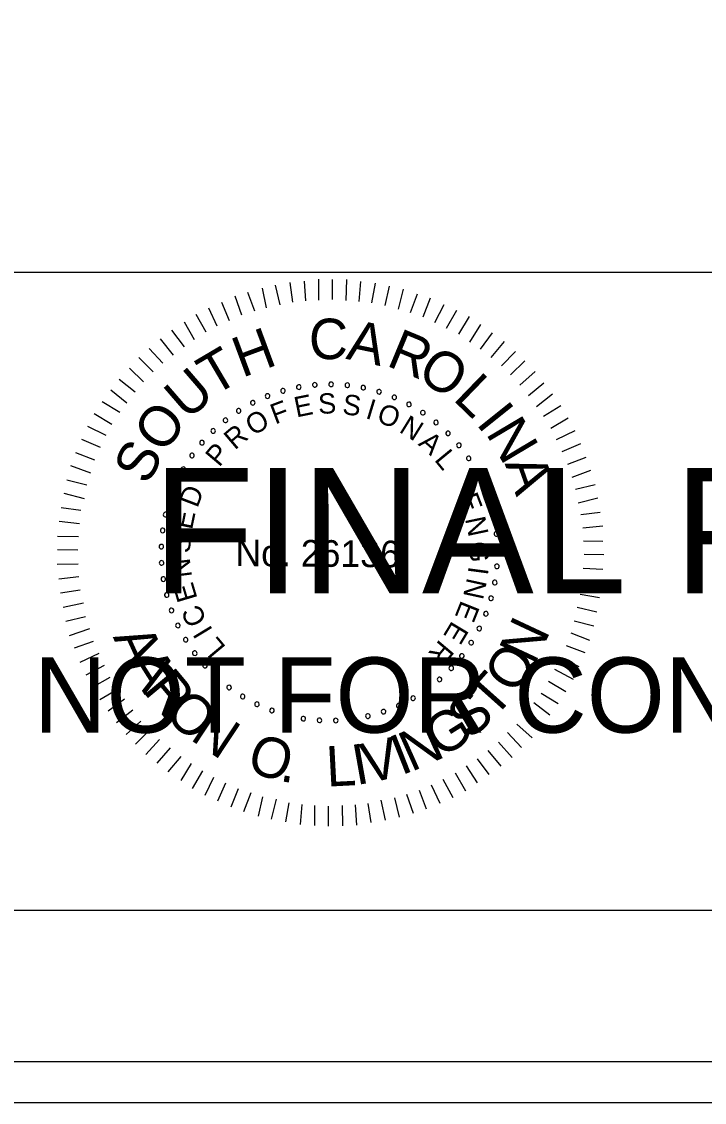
# Model space of a CAD drawing. Extents: x 967 to 1746, y 964 to 7904.
# Drawn here: x 1170.56 to 1189.3, y 7123.72 to 7153.36 of the extents above; entities that cross this region are included whole.
import ezdxf

# ---------------------------------------------------------------- set-up
doc = ezdxf.new("R2010")
doc.units = 0
for name, color, linetype in [('RD_SHT_Bndy', 7, 'Continuous'), ('RD_SHT_IplotShp', 7, 'Continuous'), ('RD_SHT_Misc1', 7, 'Continuous'), ('RD_SHT_Misc2', 7, 'Continuous'), ('RD_Sketch1', 7, 'Continuous')]:
    doc.layers.add(name, color=color, linetype=linetype)

msp = doc.modelspace()

# ---------------------------------------------------------------- linework, layer by layer
at = {"layer": 'RD_SHT_Bndy'}
for p, q in [((996.114, 7146.486), (1323.886, 7146.486)), ((1323.886, 7128.983), (996.114, 7128.983))]:
    msp.add_line(p, q, dxfattribs=at)
at = {"layer": 'RD_SHT_IplotShp'}
for points in [[(967.409, 7123.72), (1326.285, 7123.72), (1326.285, 7343.72), (967.409, 7343.72)], [(988.525, 7124.84), (1326.285, 7124.84), (1326.285, 7342.6), (988.525, 7342.6)]]:
    msp.add_lwpolyline(points, close=True, dxfattribs=at)
at = {"layer": 'RD_SHT_Misc1'}
for p, q in [((1178.01, 7145.663), (1177.93, 7146.209)), ((1178.364, 7145.699), (1178.33, 7146.244)), ((1178.717, 7145.719), (1178.722, 7146.295)), ((1179.093, 7145.739), (1179.098, 7146.292)), ((1179.469, 7145.713), (1179.489, 7146.288)), ((1179.829, 7145.687), (1179.872, 7146.231)), ((1180.174, 7145.646), (1180.271, 7146.19)), ((1176.964, 7145.419), (1176.769, 7145.935)), ((1177.287, 7145.508), (1177.169, 7146.054)), ((1177.657, 7145.597), (1177.53, 7146.128)), ((1180.535, 7145.573), (1180.662, 7146.102)), ((1180.902, 7145.478), (1181.045, 7146.022)), ((1181.231, 7145.384), (1181.428, 7145.896)), ((1176.264, 7145.156), (1176.053, 7145.657)), ((1176.61, 7145.306), (1176.423, 7145.83)), ((1181.584, 7145.265), (1181.78, 7145.786)), ((1181.905, 7145.109), (1182.154, 7145.606)), ((1175.624, 7144.846), (1175.352, 7145.332)), ((1175.933, 7145.005), (1175.699, 7145.506)), ((1182.226, 7144.953), (1182.506, 7145.45)), ((1182.562, 7144.789), (1182.85, 7145.27)), ((1175.308, 7144.634), (1175.036, 7145.12)), ((1182.86, 7144.572), (1183.163, 7145.053)), ((1174.729, 7144.217), (1174.372, 7144.665)), ((1175.03, 7144.445), (1174.681, 7144.9)), ((1183.158, 7144.378), (1183.484, 7144.828)), ((1174.435, 7143.997), (1174.062, 7144.399)), ((1183.447, 7144.145), (1183.811, 7144.587)), ((1174.172, 7143.753), (1173.776, 7144.148)), ((1183.729, 7143.92), (1184.116, 7144.316)), ((1173.909, 7143.479), (1173.52, 7143.858)), ((1183.98, 7143.672), (1184.368, 7144.061)), ((1173.684, 7143.197), (1173.242, 7143.546)), ((1184.232, 7143.394), (1184.657, 7143.767)), ((1173.451, 7142.9), (1173.009, 7143.256)), ((1184.475, 7143.108), (1184.892, 7143.45)), ((1173.257, 7142.64), (1172.776, 7142.936)), ((1184.687, 7142.807), (1185.128, 7143.156)), ((1173.039, 7142.312), (1172.559, 7142.6)), ((1184.885, 7142.544), (1185.355, 7142.832)), ((1185.081, 7142.213), (1185.56, 7142.493)), ((1172.883, 7142.006), (1172.379, 7142.256)), ((1185.24, 7141.904), (1185.756, 7142.145)), ((1172.727, 7141.677), (1172.215, 7141.904)), ((1185.399, 7141.573), (1185.907, 7141.791)), ((1172.571, 7141.333), (1172.051, 7141.53)), ((1185.549, 7141.226), (1186.057, 7141.414)), ((1172.461, 7140.974), (1171.91, 7141.178)), ((1185.669, 7140.865), (1186.185, 7141.06)), ((1172.351, 7140.652), (1171.807, 7140.787)), ((1185.759, 7140.541), (1186.297, 7140.667)), ((1172.286, 7140.276), (1171.727, 7140.419)), ((1185.832, 7140.165), (1186.371, 7140.298)), ((1172.191, 7139.955), (1171.647, 7140.029)), ((1172.15, 7139.587), (1171.598, 7139.653)), ((1185.906, 7139.842), (1186.436, 7139.906)), ((1185.964, 7139.473), (1186.51, 7139.53)), ((1172.124, 7139.234), (1171.548, 7139.239)), ((1185.977, 7139.12), (1186.514, 7139.115)), ((1172.105, 7138.866), (1171.545, 7138.871)), ((1185.997, 7138.751), (1186.542, 7138.747)), ((1172.118, 7138.482), (1171.542, 7138.471)), ((1185.971, 7138.368), (1186.508, 7138.348)), ((1172.138, 7138.136), (1171.585, 7138.072)), ((1185.952, 7138.022), (1186.497, 7137.949)), ((1172.173, 7137.768), (1171.627, 7137.688)), ((1185.888, 7137.655), (1186.417, 7137.566)), ((1172.262, 7137.414), (1171.701, 7137.296)), ((1185.808, 7137.302), (1186.345, 7137.175)), ((1172.321, 7137.037), (1171.774, 7136.911)), ((1172.425, 7136.707), (1171.871, 7136.519)), ((1185.729, 7136.926), (1186.265, 7136.792)), ((1185.634, 7136.597), (1186.146, 7136.401)), ((1172.53, 7136.36), (1172.007, 7136.173)), ((1185.508, 7136.253), (1186.013, 7136.057)), ((1172.681, 7136.029), (1172.165, 7135.788)), ((1185.352, 7135.924), (1185.857, 7135.675)), ((1172.831, 7135.705), (1172.323, 7135.441)), ((1185.188, 7135.603), (1185.7, 7135.33)), ((1172.982, 7135.374), (1172.497, 7135.094)), ((1185.024, 7135.274), (1185.498, 7134.987)), ((1173.194, 7135.042), (1172.709, 7134.762)), ((1184.822, 7134.946), (1185.288, 7134.658)), ((1173.384, 7134.78), (1172.936, 7134.453)), ((1184.62, 7134.687), (1185.055, 7134.353)), ((1173.612, 7134.478), (1173.164, 7134.129)), ((1184.403, 7134.389), (1184.814, 7134.033)), ((1173.832, 7134.177), (1173.437, 7133.812)), ((1184.155, 7134.092), (1184.574, 7133.72)), ((1174.091, 7133.945), (1173.689, 7133.541)), ((1183.899, 7133.864), (1184.28, 7133.454)), ((1174.35, 7133.674), (1173.97, 7133.263)), ((1174.64, 7133.442), (1174.275, 7133.022)), ((1183.644, 7133.597), (1184.024, 7133.18)), ((1174.937, 7133.209), (1174.58, 7132.782)), ((1183.065, 7133.141), (1183.384, 7132.709)), ((1183.358, 7133.37), (1183.715, 7132.944)), ((1175.212, 7133.014), (1174.932, 7132.549)), ((1175.525, 7132.812), (1175.245, 7132.331)), ((1182.764, 7132.952), (1183.059, 7132.482)), ((1175.83, 7132.633), (1175.588, 7132.136)), ((1182.124, 7132.581), (1182.396, 7132.08)), ((1182.463, 7132.755), (1182.743, 7132.269)), ((1176.159, 7132.477), (1175.94, 7131.98)), ((1176.503, 7132.321), (1176.307, 7131.816)), ((1181.476, 7132.28), (1181.664, 7131.771)), ((1181.8, 7132.431), (1182.041, 7131.93)), ((1176.855, 7132.211), (1176.651, 7131.69)), ((1177.177, 7132.1), (1177.05, 7131.572)), ((1177.545, 7132.036), (1177.409, 7131.484)), ((1177.897, 7131.933), (1177.808, 7131.412)), ((1180.423, 7132.012), (1180.541, 7131.458)), ((1180.791, 7132.07), (1180.926, 7131.54)), ((1181.122, 7132.175), (1181.31, 7131.652)), ((1178.25, 7131.892), (1178.207, 7131.34)), ((1178.603, 7131.866), (1178.598, 7131.313)), ((1178.978, 7131.84), (1178.974, 7131.295)), ((1179.355, 7131.86), (1179.365, 7131.307)), ((1179.715, 7131.88), (1179.749, 7131.327)), ((1180.061, 7131.915), (1180.149, 7131.393))]:
    msp.add_line(p, q, dxfattribs=at)
for centre, start, end in [((1177.734, 7143.235), 16.1422, 196.1422), ((1177.734, 7143.235), 196.1422, 16.1422), ((1178.168, 7143.337), 10.6038, 190.6038), ((1178.168, 7143.337), 190.6038, 10.6038), ((1178.609, 7143.397), 5.0653, 185.0653), ((1178.609, 7143.397), 185.0653, 5.0653), ((1179.055, 7143.414), 359.5268, 179.5268), ((1179.055, 7143.414), 179.5268, 359.5268), ((1179.5, 7143.388), 353.9884, 173.9884), ((1179.5, 7143.388), 173.9884, 353.9884), ((1179.94, 7143.319), 168.4499, 348.4499), ((1179.94, 7143.319), 348.4499, 168.4499), ((1180.372, 7143.208), 162.9114, 342.9114), ((1180.372, 7143.208), 342.9114, 162.9114), ((1176.906, 7142.908), 27.2191, 207.2191), ((1176.906, 7142.908), 207.2191, 27.2191), ((1177.312, 7143.091), 21.6807, 201.6807), ((1177.312, 7143.091), 201.6807, 21.6807), ((1180.79, 7143.056), 157.373, 337.373), ((1180.79, 7143.056), 337.373, 157.373), ((1181.193, 7142.864), 151.8345, 331.8345), ((1181.193, 7142.864), 331.8345, 151.8345), ((1176.52, 7142.686), 32.7576, 212.7576), ((1176.52, 7142.686), 212.7576, 32.7576), ((1181.574, 7142.634), 146.2961, 326.2961), ((1181.574, 7142.634), 326.2961, 146.2961), ((1176.156, 7142.428), 38.2961, 218.2961), ((1176.156, 7142.428), 218.2961, 38.2961), ((1181.932, 7142.368), 140.7576, 320.7576), ((1181.932, 7142.368), 320.7576, 140.7576), ((1175.82, 7142.135), 43.8345, 223.8345), ((1175.82, 7142.135), 223.8345, 43.8345), ((1182.263, 7142.069), 135.2191, 315.2191), ((1182.263, 7142.069), 315.2191, 135.2191), ((1175.513, 7141.812), 49.373, 229.373), ((1175.513, 7141.812), 229.373, 49.373), ((1182.563, 7141.74), 129.6807, 309.6807), ((1182.563, 7141.74), 309.6807, 129.6807), ((1175.239, 7141.461), 54.9114, 234.9114), ((1175.239, 7141.461), 234.9114, 54.9114), ((1182.83, 7141.383), 124.1422, 304.1422), ((1182.83, 7141.383), 304.1422, 124.1422), ((1175, 7141.085), 60.4499, 240.4499), ((1175, 7141.085), 240.4499, 60.4499), ((1183.061, 7141.002), 118.6038, 298.6038), ((1183.061, 7141.002), 298.6038, 118.6038), ((1174.798, 7140.687), 65.9884, 245.9884), ((1174.798, 7140.687), 245.9884, 65.9884), ((1183.255, 7140.601), 113.0653, 293.0653), ((1183.255, 7140.601), 293.0653, 113.0653), ((1174.636, 7140.272), 71.5268, 251.5268), ((1174.636, 7140.272), 251.5268, 71.5268), ((1183.408, 7140.182), 107.5268, 287.5268), ((1183.408, 7140.182), 287.5268, 107.5268), ((1174.514, 7139.843), 77.0653, 257.0653), ((1174.514, 7139.843), 257.0653, 77.0653), ((1183.521, 7139.751), 101.9884, 281.9884), ((1183.521, 7139.751), 281.9884, 101.9884), ((1174.435, 7139.405), 82.6038, 262.6038), ((1174.435, 7139.405), 262.6038, 82.6038), ((1183.592, 7139.311), 96.4499, 276.4499), ((1183.592, 7139.311), 276.4499, 96.4499), ((1174.398, 7138.961), 88.1422, 268.1422), ((1174.398, 7138.961), 268.1422, 88.1422), ((1183.619, 7138.866), 90.9114, 270.9114), ((1183.619, 7138.866), 270.9114, 90.9114), ((1174.404, 7138.515), 93.6807, 273.6807), ((1174.404, 7138.515), 273.6807, 93.6807), ((1183.604, 7138.421), 85.373, 265.373), ((1183.604, 7138.421), 265.373, 85.373), ((1174.453, 7138.072), 99.2191, 279.2191), ((1174.453, 7138.072), 279.2191, 99.2191), ((1183.546, 7137.979), 79.8345, 259.8345), ((1183.546, 7137.979), 259.8345, 79.8345), ((1174.545, 7137.636), 104.7576, 284.7576), ((1174.545, 7137.636), 284.7576, 104.7576), ((1183.445, 7137.545), 74.2961, 254.2961), ((1183.445, 7137.545), 254.2961, 74.2961), ((1174.678, 7137.211), 110.2961, 290.2961), ((1174.678, 7137.211), 290.2961, 110.2961), ((1183.303, 7137.122), 68.7576, 248.7576), ((1183.303, 7137.122), 248.7576, 68.7576), ((1174.852, 7136.8), 115.8345, 295.8345), ((1174.852, 7136.8), 295.8345, 115.8345), ((1183.121, 7136.716), 63.2191, 243.2191), ((1183.121, 7136.716), 243.2191, 63.2191), ((1175.065, 7136.409), 121.373, 301.373), ((1175.065, 7136.409), 301.373, 121.373), ((1182.9, 7136.328), 57.6807, 237.6807), ((1182.9, 7136.328), 237.6807, 57.6807), ((1175.314, 7136.039), 126.9114, 306.9114), ((1175.314, 7136.039), 306.9114, 126.9114), ((1182.643, 7135.964), 52.1422, 232.1422), ((1182.643, 7135.964), 232.1422, 52.1422), ((1175.598, 7135.696), 132.4499, 312.4499), ((1175.598, 7135.696), 312.4499, 132.4499), ((1182.353, 7135.627), 46.6038, 226.6038), ((1182.353, 7135.627), 226.6038, 46.6038), ((1175.914, 7135.381), 137.9884, 317.9884), ((1175.914, 7135.381), 317.9884, 137.9884), ((1182.03, 7135.319), 41.0653, 221.0653), ((1182.03, 7135.319), 221.0653, 41.0653), ((1176.258, 7135.099), 143.5268, 323.5268), ((1176.258, 7135.099), 323.5268, 143.5268), ((1176.629, 7134.851), 329.0653, 149.0653), ((1181.68, 7135.043), 35.5268, 215.5268), ((1181.68, 7135.043), 215.5268, 35.5268), ((1176.629, 7134.851), 149.0653, 329.0653), ((1177.021, 7134.639), 154.6038, 334.6038), ((1177.021, 7134.639), 334.6038, 154.6038), ((1180.908, 7134.6), 24.4499, 204.4499), ((1180.908, 7134.6), 204.4499, 24.4499), ((1181.305, 7134.803), 29.9884, 209.9884), ((1181.305, 7134.803), 209.9884, 29.9884), ((1177.432, 7134.467), 160.1422, 340.1422), ((1177.432, 7134.467), 340.1422, 160.1422), ((1177.858, 7134.335), 165.6807, 345.6807), ((1177.858, 7134.335), 345.6807, 165.6807), ((1178.294, 7134.245), 351.2191, 171.2191), ((1179.627, 7134.232), 7.8345, 187.8345), ((1180.065, 7134.313), 13.373, 193.373), ((1180.065, 7134.313), 193.373, 13.373), ((1180.494, 7134.436), 18.9114, 198.9114), ((1180.494, 7134.436), 198.9114, 18.9114), ((1178.294, 7134.245), 171.2191, 351.2191), ((1178.737, 7134.198), 356.7576, 176.7576), ((1178.737, 7134.198), 176.7576, 356.7576), ((1179.183, 7134.193), 2.2961, 182.2961), ((1179.183, 7134.193), 182.2961, 2.2961), ((1179.627, 7134.232), 187.8345, 7.8345)]:
    msp.add_arc(centre, 0.0627, start, end, dxfattribs=at)
at = {"layer": 'RD_Sketch1'}
msp.add_lwpolyline([(967.409, 7123.72), (1326.285, 7123.72), (1326.285, 7343.72), (967.409, 7343.72)], close=True, dxfattribs=at)

# ---------------------------------------------------------------- texts
at = {"layer": 'RD_SHT_Misc1'}
for s, height, rotation, p in [('C', 1.11, 359.5482, (1178.442, 7144.108)), ('A', 1.11, 348.1981, (1179.439, 7144.115)), ('H', 1.11, 20.3637, (1176.614, 7143.587)), ('R', 1.11, 337.4344, (1180.541, 7143.937)), ('T', 1.11, 30.4992, (1175.828, 7143.072)), ('O', 1.108, 326.5869, (1181.366, 7143.609)), ('U', 1.11, 40.8022, (1175.102, 7142.403)), ('L', 1.11, 315.9488, (1182.373, 7143.003)), ('F', 0.557, 20.6127, (1177.52, 7142.309)), ('E', 0.557, 11.4103, (1178.103, 7142.503)), ('S', 0.557, 2.208, (1178.709, 7142.601)), ('S', 0.557, 352.6608, (1179.346, 7142.599)), ('I', 0.557, 343.1136, (1179.975, 7142.491)), ('I', 1.11, 308.6613, (1183.011, 7142.338)), ('O', 1.11, 52.0267, (1174.435, 7141.474)), ('O', 0.557, 30.8477, (1176.917, 7141.987)), ('O', 0.557, 338.4392, (1180.274, 7142.401)), ('N', 0.557, 328.2042, (1180.896, 7142.12)), ('N', 1.11, 300.7037, (1183.285, 7142.075)), ('R', 0.557, 40.3949, (1176.415, 7141.594)), ('A', 0.557, 318.657, (1181.424, 7141.762)), ('S', 1.108, 63.2511, (1174.029, 7140.619)), ('P', 0.557, 49.9421, (1175.985, 7141.124)), ('L', 0.557, 309.4546, (1181.869, 7141.339)), ('A', 1.11, 289.4792, (1183.814, 7141.243)), ('D', 0.557, 69.0364, (1175.386, 7140.003)), ('E', 0.557, 291.049, (1182.53, 7140.307)), ('E', 0.557, 78.2388, (1175.238, 7139.407)), ('N', 0.557, 281.8466, (1182.728, 7139.726)), ('S', 0.557, 87.786, (1175.187, 7138.772)), ('No. 26136', 0.7311, 359.5268, (1176.429, 7138.43)), ('G', 0.557, 272.2995, (1182.833, 7139.097)), ('N', 0.557, 97.3332, (1175.242, 7138.137)), ('I', 0.557, 262.4084, (1182.83, 7138.437)), ('E', 0.557, 106.5355, (1175.394, 7137.541)), ('N', 0.557, 257.7339, (1182.789, 7138.127)), ('C', 0.557, 116.4266, (1175.661, 7136.938)), ('E', 0.557, 248.1867, (1182.628, 7137.511)), ('N', 1.105, 64.8922, (1184.632, 7135.684)), ('I', 0.557, 121.1011, (1175.823, 7136.67)), ('E', 0.557, 238.9844, (1182.378, 7136.949)), ('A', 1.105, 294.7297, (1173.062, 7136.486)), ('L', 0.557, 129.9595, (1176.187, 7136.204)), ('R', 0.557, 229.782, (1182.041, 7136.435)), ('O', 1.105, 56.2059, (1184.102, 7134.874)), ('A', 1.105, 302.2892, (1173.414, 7135.72)), ('R', 1.105, 309.8487, (1173.865, 7135.007)), ('T', 1.105, 48.2685, (1183.515, 7134.211)), ('O', 1.105, 317.7861, (1174.434, 7134.33)), ('S', 1.105, 40.3311, (1182.842, 7133.636)), ('N', 1.105, 326.4725, (1175.158, 7133.686)), ('G', 1.105, 32.0198, (1182.059, 7133.14)), ('N', 1.105, 24.0824, (1181.252, 7132.776)), ('O', 1.105, 342.3472, (1176.697, 7132.82)), ('V', 1.105, 12.7741, (1180.033, 7132.457)), ('I', 1.105, 21.4605, (1180.976, 7132.681)), ('L', 1.105, 2.9677, (1178.943, 7132.379)), ('I', 1.105, 10.1523, (1179.743, 7132.418)), ('.', 1.105, 351.0336, (1177.623, 7132.536))]:
    msp.add_text(s, height=height, rotation=rotation, dxfattribs=at).set_placement(p)
at = {"layer": 'RD_SHT_Misc2'}
for s, height, p in [('FINAL PLANS', 3.4375, (1174.145, 7137.685)), ('NOT FOR CONSTRUCTION', 2.0625, (1170.901, 7133.86))]:
    msp.add_text(s, height=height, dxfattribs=at).set_placement(p)

doc.saveas('drawing.dxf')
